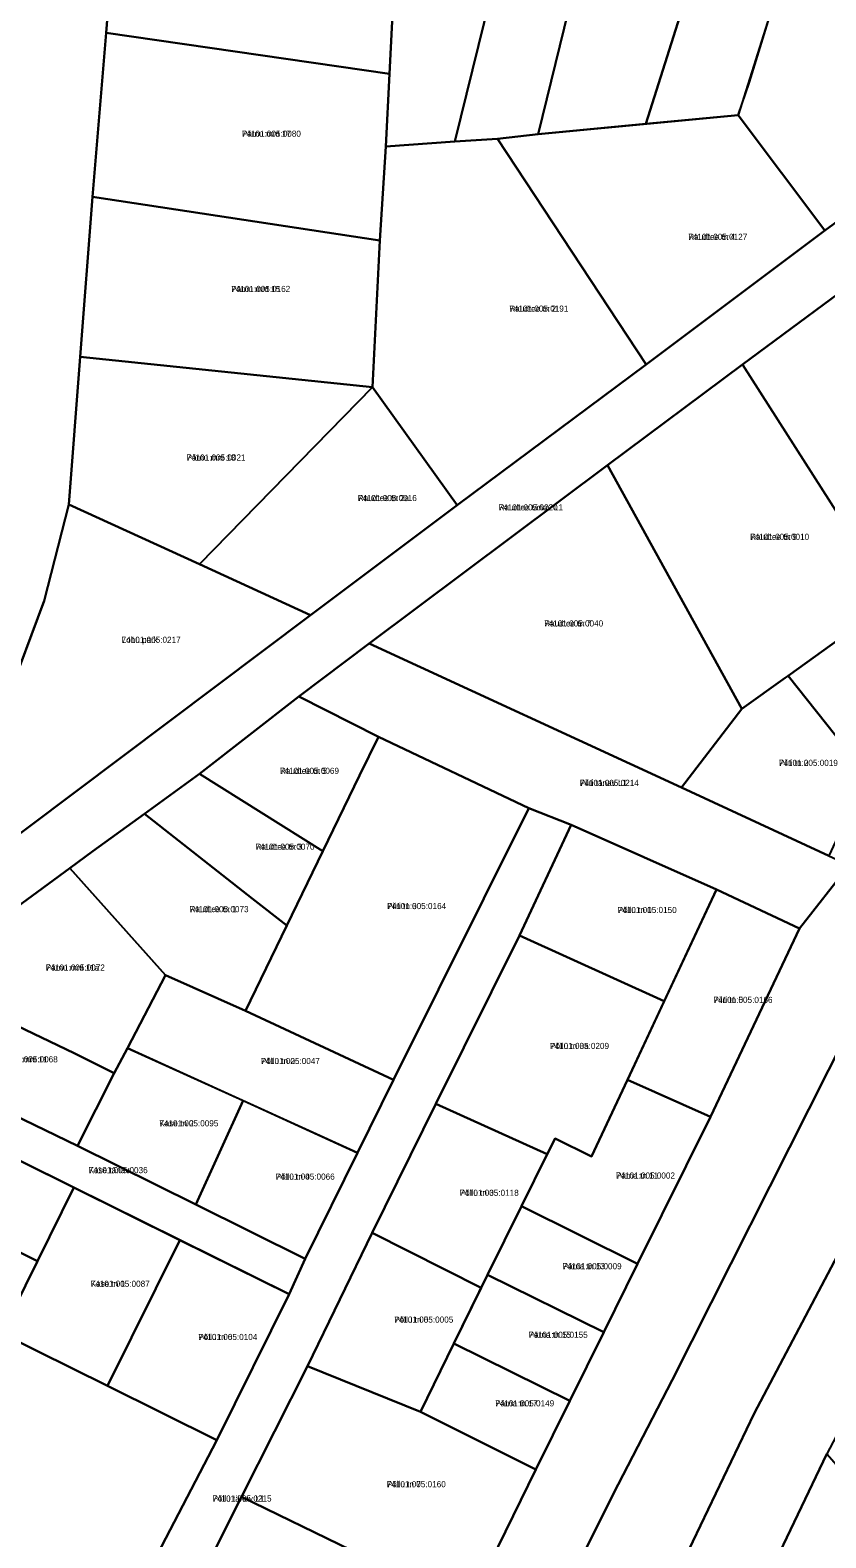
# Model space of a CAD drawing. Extents: x 524000 to 564260, y 6469338 to 6496391.
# Drawn here: x 537778.5 to 537974.1, y 6473256.9 to 6473627.5 of the extents above; entities that cross this region are included whole.
import ezdxf

# ---------------------------------------------------------------- set-up
doc = ezdxf.new("R2010")
doc.units = 0
for name, color, linetype in [('L_AADRESS', 7, 'Continuous'), ('PIIR', 7, 'Continuous'), ('TUNNUS', 7, 'Continuous')]:
    doc.layers.add(name, color=color, linetype=linetype)

msp = doc.modelspace()

# ---------------------------------------------------------------- linework, layer by layer
at = {"layer": 'PIIR'}
for points in [[(537868.94, 6473658.96), (537879.29, 6473679.46), (537900.22, 6473670.75), (537882.86, 6473600.14), (537865.94, 6473598.97), (537866.86, 6473616.77)], [(537882.86, 6473600.14), (537900.22, 6473670.75), (537918.34, 6473663.21), (537903.39, 6473601.94), (537893.33, 6473600.87)], [(537800.52, 6473668.4), (537868.94, 6473658.96), (537866.86, 6473616.77), (537797.17, 6473626.89)], [(537918.34, 6473663.21), (537944.94, 6473652.49), (537929.84, 6473604.5), (537903.39, 6473601.94)], [(537944.94, 6473652.49), (537964.47, 6473644.63), (537952.53, 6473606.66), (537929.84, 6473604.5)], [(537952.53, 6473606.66), (537955.27, 6473614.75), (537964.47, 6473644.63), (538010.52, 6473624.6), (538014, 6473607.71), (537973.77, 6473578.26)], [(538010.52, 6473624.6), (538042.3, 6473611.92), (538020.62, 6473595.63), (537987.2, 6473570.28), (537953.54, 6473545.34), (537920.36, 6473520.58), (537861.87, 6473476.79), (537844.52, 6473463.73), (537820.14, 6473444.71), (537806.67, 6473434.95), (537793.95, 6473425.71), (537788.26, 6473421.58), (537751.21, 6473394.37), (537754.58, 6473413.98), (537847.44, 6473483.75), (537883.48, 6473510.79), (537929.92, 6473545.34), (537973.77, 6473578.26), (538014, 6473607.71)], [(537797.17, 6473626.89), (537866.86, 6473616.77), (537865.94, 6473598.97), (537864.43, 6473575.81), (537793.83, 6473586.58)], [(537893.33, 6473600.87), (537903.39, 6473601.94), (537952.53, 6473606.66), (537973.77, 6473578.26), (537929.92, 6473545.34)], [(537929.92, 6473545.34), (537883.48, 6473510.79), (537862.63, 6473539.81), (537864.43, 6473575.81), (537865.94, 6473598.97), (537882.86, 6473600.14), (537893.33, 6473600.87)], [(537793.83, 6473586.58), (537864.43, 6473575.81), (537862.63, 6473539.81), (537790.85, 6473547.25)], [(537987.2, 6473570.28), (538012.22, 6473528.71), (537979.65, 6473504.52), (537953.54, 6473545.34)], [(537862.63, 6473539.81), (537820.17, 6473496.25), (537788.07, 6473510.95), (537790.85, 6473547.25)], [(537953.54, 6473545.34), (537979.65, 6473504.52), (537990.53, 6473487.32), (537964.78, 6473468.79), (537964.02, 6473468.33), (537953.42, 6473460.71), (537920.36, 6473520.58)], [(537883.48, 6473510.79), (537847.44, 6473483.75), (537820.17, 6473496.25), (537862.63, 6473539.81)], [(537920.36, 6473520.58), (537953.42, 6473460.71), (537938.56, 6473441.35), (537861.87, 6473476.79)], [(537788.07, 6473510.95), (537820.17, 6473496.25), (537847.44, 6473483.75), (537754.58, 6473413.98), (537781.94, 6473487.23)], [(537987.87, 6473439.78), (537964.78, 6473468.79), (537990.53, 6473487.32), (538004.74, 6473476.19)], [(537938.56, 6473441.35), (537974.82, 6473424.59), (537979.81, 6473422.29), (537967.61, 6473406.75), (537947.16, 6473416.32), (537911.45, 6473432.19), (537901.08, 6473436.32), (537864.09, 6473453.8), (537844.52, 6473463.73), (537861.87, 6473476.79)], [(537964.78, 6473468.79), (537987.87, 6473439.78), (537982.5, 6473428.1), (537977.5, 6473430.4), (537974.82, 6473424.59), (537938.56, 6473441.35), (537953.42, 6473460.71), (537964.02, 6473468.33)], [(537844.52, 6473463.73), (537864.09, 6473453.8), (537859.48, 6473444.32), (537850.45, 6473425.73), (537820.14, 6473444.71)], [(537850.45, 6473425.73), (537859.48, 6473444.32), (537864.09, 6473453.8), (537901.08, 6473436.32), (537867.79, 6473369.49), (537831.42, 6473386.51)], [(537820.14, 6473444.71), (537850.45, 6473425.73), (537841.59, 6473407.45), (537833.11, 6473414.13), (537806.67, 6473434.95)], [(537911.45, 6473432.19), (537898.77, 6473405), (537878.24, 6473363.63), (537862.56, 6473331.9), (537846.66, 6473299.16), (537830.46, 6473267.01), (537814.16, 6473234.46), (537800.74, 6473207.08), (537787.69, 6473180.48), (537778.82, 6473162.48), (537769.71, 6473144.74), (537760.91, 6473126.77), (537752.14, 6473108.89), (537735.25, 6473107.1), (537744.18, 6473124.88), (537753.17, 6473143.42), (537772.14, 6473180.53), (537824.43, 6473280.98), (537842.16, 6473316.83), (537846.14, 6473325.5), (537858.94, 6473351.56), (537867.79, 6473369.49), (537901.08, 6473436.32)], [(537841.59, 6473407.45), (537831.42, 6473386.51), (537811.8, 6473395.27), (537788.26, 6473421.58), (537793.95, 6473425.71), (537806.67, 6473434.95), (537833.11, 6473414.13)], [(537947.16, 6473416.32), (537934.32, 6473388.86), (537898.77, 6473405), (537911.45, 6473432.19)], [(537788.26, 6473421.58), (537811.8, 6473395.27), (537802.49, 6473377.32), (537799.19, 6473371.18), (537789.35, 6473376.06), (537751.21, 6473394.37)], [(537925.3, 6473369.56), (537947.16, 6473416.32), (537967.61, 6473406.75), (537945.7, 6473360.45)], [(537898.77, 6473405), (537934.32, 6473388.86), (537925.3, 6473369.56), (537916.47, 6473350.7), (537907.5, 6473355.14), (537905.61, 6473351.26), (537878.24, 6473363.63)], [(537867.79, 6473369.49), (537858.94, 6473351.56), (537802.49, 6473377.32), (537811.8, 6473395.27), (537831.42, 6473386.51)], [(537751.21, 6473394.37), (537789.35, 6473376.06), (537799.19, 6473371.18), (537790.18, 6473353.27), (537742.55, 6473376.34)], [(537742.55, 6473376.34), (537790.18, 6473353.27), (537819.27, 6473338.86), (537846.14, 6473325.5), (537842.16, 6473316.83), (537815.21, 6473330.18), (537788.95, 6473343.2), (537737.89, 6473368.51)], [(537802.49, 6473377.32), (537830.84, 6473364.47), (537819.27, 6473338.86), (537790.18, 6473353.27), (537799.19, 6473371.18)], [(537905.68, 6473351.42), (537907.5, 6473355.14), (537916.47, 6473350.7), (537925.3, 6473369.56), (537945.7, 6473360.45), (537927.81, 6473324.33), (537899.26, 6473338.44)], [(537789.29, 6473343.02), (537780.35, 6473324.94), (537728.39, 6473350.68), (537737.89, 6473368.51)], [(537830.84, 6473364.47), (537858.94, 6473351.56), (537846.14, 6473325.5), (537819.27, 6473338.86)], [(537878.24, 6473363.63), (537905.61, 6473351.26), (537899.26, 6473338.44), (537890.93, 6473321.59), (537889.34, 6473318.37), (537862.56, 6473331.9)], [(537728.39, 6473350.68), (537780.35, 6473324.94), (537771.55, 6473307.16), (537724.12, 6473330.67), (537718.74, 6473333.33)], [(537780.35, 6473324.94), (537789.29, 6473343.02), (537815.28, 6473330.15), (537797.54, 6473294.29), (537771.55, 6473307.16)], [(537927.81, 6473324.33), (537919.48, 6473307.48), (537890.93, 6473321.59), (537899.26, 6473338.44)], [(537862.56, 6473331.9), (537889.34, 6473318.37), (537882.6, 6473304.74), (537874.47, 6473287.9), (537846.66, 6473299.16)], [(537726.44, 6473156.95), (537699.68, 6473170.07), (537672.88, 6473183.77), (537646.08, 6473197.47), (537632.7, 6473204.36), (537624, 6473208.76), (537627.57, 6473215.35), (537724.12, 6473330.67), (537771.55, 6473307.16), (537797.54, 6473294.29), (537824.43, 6473280.98), (537772.14, 6473180.53), (537745.72, 6473193.99)], [(537815.28, 6473330.15), (537842.16, 6473316.83), (537824.43, 6473280.98), (537797.54, 6473294.29)], [(537882.6, 6473304.74), (537890.93, 6473321.59), (537919.48, 6473307.48), (537911.15, 6473290.63)], [(537882.6, 6473304.74), (537911.15, 6473290.63), (537902.82, 6473273.77), (537874.47, 6473287.9)], [(537830.46, 6473267.01), (537846.66, 6473299.16), (537874.47, 6473287.9), (537902.82, 6473273.77), (537886.07, 6473239.61), (537857.45, 6473253.92)], [(537974.33, 6473277.57), (538003.68, 6473244.12), (537980.89, 6473223.78), (537960.04, 6473247.79)], [(537830.46, 6473267.01), (537857.45, 6473253.92), (537844.93, 6473228.59), (537841.38, 6473221.39), (537814.16, 6473234.46)]]:
    msp.add_lwpolyline(points, close=True, dxfattribs=at)
for points in [[(537800.52, 6473668.4), (537797.17, 6473626.89), (537793.83, 6473586.58), (537790.85, 6473547.25), (537788.07, 6473510.95), (537781.94, 6473487.23), (537754.58, 6473413.98)], [(537899.34, 6473222.91), (537923.04, 6473270.09), (537936.29, 6473295.74), (537974.68, 6473371.89), (537998.55, 6473419.28), (538017.73, 6473457.41), (538037.04, 6473487.48), (538054.77, 6473515.09), (538072.04, 6473537.32), (538089.08, 6473558.08), (538092.25, 6473561.84), (538094.7, 6473564.49), (538096.73, 6473566.39), (538111.56, 6473545.72), (538084.14, 6473511.85), (538056.41, 6473470.88), (538046.02, 6473453.04), (538031.94, 6473428.82), (538009.78, 6473384.2), (538008.07, 6473386.14), (538002.94, 6473375.76), (537956.46, 6473287.47), (537881.05, 6473130.21)], [(537886.07, 6473239.61), (537902.82, 6473273.77), (537911.15, 6473290.63), (537919.48, 6473307.48), (537927.81, 6473324.33), (537945.7, 6473360.45), (537967.61, 6473406.75), (537979.81, 6473422.29), (537982.5, 6473428.1), (537987.87, 6473439.78), (538004.74, 6473476.19), (538025, 6473507.48), (538031.44, 6473496.78), (538037.04, 6473487.48), (538017.73, 6473457.41), (537998.55, 6473419.28), (537974.68, 6473371.89), (537936.29, 6473295.74), (537923.04, 6473270.09), (537899.34, 6473222.91)], [(537881.05, 6473130.21), (537956.46, 6473287.47), (538002.94, 6473375.76), (538010.97, 6473366.26), (537991.51, 6473329.38), (537996.31, 6473322.65), (537979.58, 6473287.68), (537974.33, 6473277.57), (537960.04, 6473247.79)]]:
    msp.add_lwpolyline(points, dxfattribs=at)

# ---------------------------------------------------------------- texts
at = {"layer": 'L_AADRESS'}
for s, p in [('Pärnu mnt 17', (537830.56, 6473601.35)), ('Raudtee tn 4', (537940.24, 6473576)), ('Pärnu mnt 15', (537827.93, 6473563.19)), ('Raudtee tn 2', (537896.28, 6473558.35)), ('Pärnu mnt 13', (537816.96, 6473521.75)), ('Raudtee tn 2a', (537859.04, 6473511.78)), ('Raudtee tänav L1', (537893.64, 6473509.49)), ('Raudtee tn 9', (537955.45, 6473502.26)), ('Raudtee tn 7', (537904.84, 6473480.96)), ('Lohu park', (537801.01, 6473476.94)), ('Piiri tn 2', (537962.51, 6473446.69)), ('Raudtee tn 5', (537839.92, 6473444.73)), ('Piiri tänav L1', (537913.6, 6473441.77)), ('Raudtee tn 3', (537833.91, 6473426.08)), ('Raudtee tn 1', (537817.7, 6473410.73)), ('Piiri tn 3', (537866.25, 6473411.49)), ('Põllu tn 1', (537922.9, 6473410.53)), ('Pärnu mnt 11a', (537782.38, 6473396.38)), ('Piiri tn 5', (537946.45, 6473388.43)), ('Põllu tn 3a', (537906.28, 6473377.11)), ('Pärnu mnt 11', (537770.81, 6473373.82)), ('Põllu tn 2', (537835.23, 6473373.41)), ('Kase tn 2', (537810.28, 6473358.09)), ('Kase tänav', (537792.9, 6473346.58)), ('Põllu tn 4', (537838.87, 6473344.99)), ('Pärna tn 11', (537922.48, 6473345.25)), ('Põllu tn 3', (537884.09, 6473341.01)), ('Pärna tn 13', (537909.37, 6473322.96)), ('Kase tn 1', (537793.41, 6473318.65)), ('Põllu tn 5', (537868, 6473309.84)), ('Põllu tn 6', (537819.85, 6473305.57)), ('Pärna tn 15', (537901.04, 6473306.11)), ('Pärna tn 17', (537892.8, 6473289.25)), ('Põllu tn 7', (537866.16, 6473269.38)), ('Põllu tänav L1', (537823.35, 6473265.86))]:
    msp.add_text(s, height=1.5, dxfattribs=at).set_placement(p)
at = {"layer": 'TUNNUS'}
for s, p in [('74101:005:0080', (537830.56, 6473601.35)), ('74101:005:0127', (537940.24, 6473576)), ('74101:005:0162', (537827.93, 6473563.19)), ('74101:005:0191', (537896.28, 6473558.35)), ('74101:005:0021', (537816.96, 6473521.75)), ('74101:005:0016', (537859.04, 6473511.78)), ('74101:005:0220', (537893.64, 6473509.49)), ('74101:005:0010', (537955.45, 6473502.26)), ('74101:005:0040', (537904.84, 6473480.96)), ('74101:005:0217', (537801.01, 6473476.94)), ('74101:005:0019', (537962.51, 6473446.69)), ('74101:005:0069', (537839.92, 6473444.73)), ('74101:005:0214', (537913.6, 6473441.77)), ('74101:005:0070', (537833.91, 6473426.08)), ('74101:005:0073', (537817.7, 6473410.73)), ('74101:005:0164', (537866.25, 6473411.49)), ('74101:005:0150', (537922.9, 6473410.53)), ('74101:005:0072', (537782.38, 6473396.38)), ('74101:005:0166', (537946.45, 6473388.43)), ('74101:005:0209', (537906.28, 6473377.11)), ('74101:005:0068', (537770.81, 6473373.82)), ('74101:005:0047', (537835.23, 6473373.41)), ('74101:005:0095', (537810.28, 6473358.09)), ('74101:005:0036', (537792.9, 6473346.58)), ('74101:005:0066', (537838.87, 6473344.99)), ('74101:005:0002', (537922.48, 6473345.25)), ('74101:005:0118', (537884.09, 6473341.01)), ('74101:005:0009', (537909.37, 6473322.96)), ('74101:005:0087', (537793.41, 6473318.65)), ('74101:005:0005', (537868, 6473309.84)), ('74101:005:0104', (537819.85, 6473305.57)), ('74101:005:0155', (537901.04, 6473306.11)), ('74101:005:0149', (537892.8, 6473289.25)), ('74101:005:0160', (537866.16, 6473269.38)), ('74101:005:0215', (537823.35, 6473265.86))]:
    msp.add_text(s, height=1.5, dxfattribs=at).set_placement(p)

doc.saveas('drawing.dxf')
